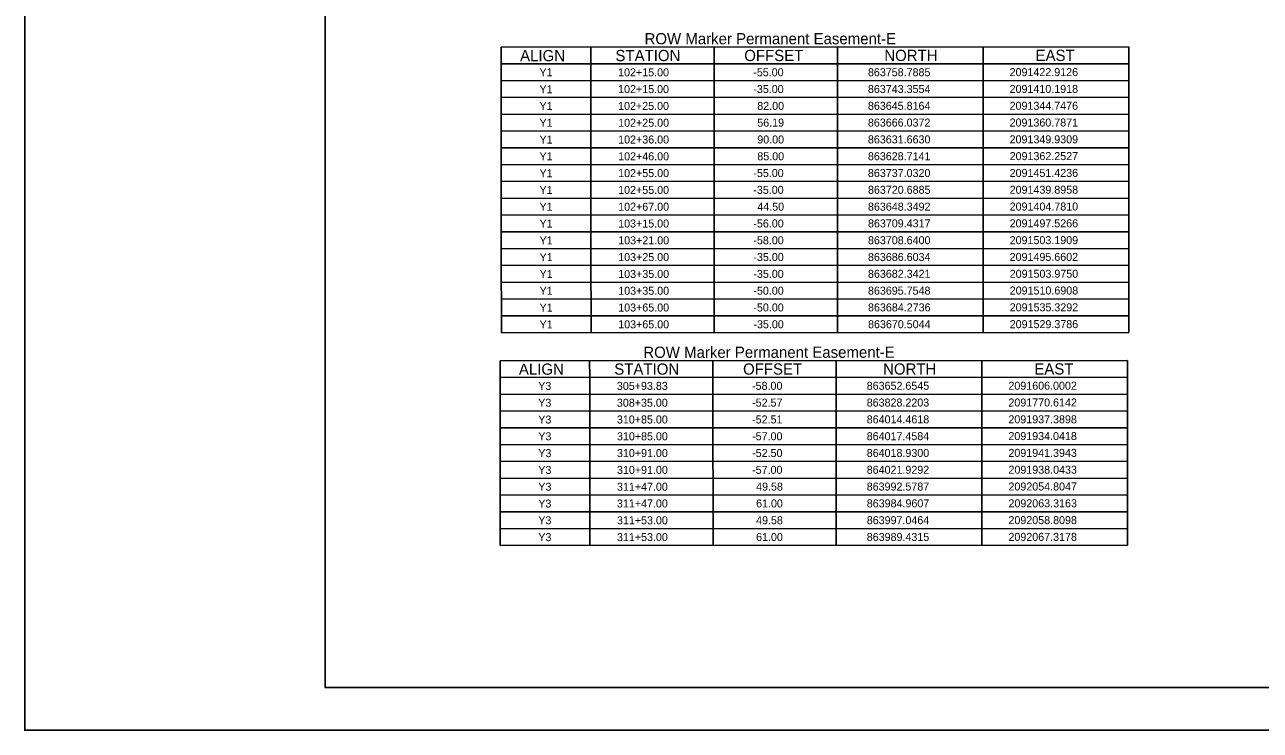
# Model space of a CAD drawing. Extents: x 2093228 to 2098328, y 861854 to 865154.
# Drawn here: x 2093228 to 2095387, y 861854 to 863087 of the extents above; entities that cross this region are included whole.
import ezdxf

# ---------------------------------------------------------------- set-up
doc = ezdxf.new("R2010")
doc.units = 0
for name, color, linetype in [('CTL Sheet Notes CELL', 7, 'Continuous'), ('CTL Sheet Table Cell', 7, 'Continuous'), ('CTL Sheet Text', 7, 'Continuous'), ('Sheet Plan CELL', 7, 'Continuous'), ('Sheet Plot Border Inside CELL', 7, 'Continuous')]:
    doc.layers.add(name, color=color, linetype=linetype)

msp = doc.modelspace()

# ---------------------------------------------------------------- linework, layer by layer
at = {"layer": 'CTL Sheet Table Cell'}
for p, q in [((2094060.9, 863048), (2095157, 863048.5)), ((2094060.9, 863048), (2094060.9, 863018.6)), ((2094217.4, 863048), (2094217.5, 863018.7)), ((2094432.8, 863048.1), (2094432.8, 863018.8)), ((2094648.1, 863048.2), (2094648.1, 863018.9)), ((2094902.5, 863048.4), (2094902.6, 863019)), ((2095157, 863048.5), (2095157, 863019.1)), ((2094060.9, 863018.6), (2095157, 863019.1)), ((2094060.9, 863018.6), (2094060.9, 862989.2)), ((2094217.5, 863018.7), (2094217.5, 862989.3)), ((2094432.8, 863018.8), (2094432.8, 862989.4)), ((2094648.1, 863018.9), (2094648.1, 862989.5)), ((2094902.6, 863019), (2094902.6, 862989.6)), ((2095157, 863019.1), (2095157, 862989.8)), ((2094060.9, 862989.2), (2095157, 862989.8)), ((2094060.9, 862989.2), (2094060.9, 862959.9)), ((2094217.5, 862989.3), (2094217.5, 862960)), ((2094432.8, 862989.4), (2094432.8, 862960.1)), ((2094648.1, 862989.5), (2094648.1, 862960.2)), ((2094902.6, 862989.6), (2094902.6, 862960.3)), ((2095157, 862989.8), (2095157.1, 862960.4)), ((2094060.9, 862959.9), (2095157.1, 862960.4)), ((2094060.9, 862959.9), (2094060.9, 862930.5)), ((2094217.5, 862960), (2094217.5, 862930.6)), ((2094432.8, 862960.1), (2094432.8, 862930.7)), ((2094648.1, 862960.2), (2094648.1, 862930.8)), ((2094902.6, 862960.3), (2094902.6, 862930.9)), ((2095157.1, 862960.4), (2095157.1, 862931)), ((2094060.9, 862930.5), (2095157.1, 862931)), ((2094060.9, 862930.5), (2094060.9, 862901.2)), ((2094217.5, 862930.6), (2094217.5, 862901.2)), ((2094432.8, 862930.7), (2094432.8, 862901.3)), ((2094648.1, 862930.8), (2094648.2, 862901.4)), ((2094902.6, 862930.9), (2094902.6, 862901.6)), ((2095157.1, 862931), (2095157.1, 862901.7)), ((2094060.9, 862901.2), (2095157.1, 862901.7)), ((2094060.9, 862901.2), (2094060.9, 862871.8)), ((2094217.5, 862901.2), (2094217.5, 862871.9)), ((2094432.8, 862901.3), (2094432.8, 862872)), ((2094648.2, 862901.4), (2094648.2, 862872.1)), ((2094902.6, 862901.6), (2094902.6, 862872.2)), ((2095157.1, 862901.7), (2095157.1, 862872.3)), ((2094060.9, 862871.8), (2095157.1, 862872.3)), ((2094060.9, 862871.8), (2094061, 862842.4)), ((2094217.5, 862871.9), (2094217.5, 862842.5)), ((2094432.8, 862872), (2094432.9, 862842.6)), ((2094648.2, 862872.1), (2094648.2, 862842.7)), ((2094902.6, 862872.2), (2094902.6, 862842.8)), ((2095157.1, 862872.3), (2095157.1, 862843)), ((2094061, 862842.4), (2095157.1, 862843)), ((2094061, 862842.4), (2094061, 862813.1)), ((2094217.5, 862842.5), (2094217.6, 862813.1)), ((2094432.9, 862842.6), (2094432.9, 862813.3)), ((2094648.2, 862842.7), (2094648.2, 862813.4)), ((2094902.6, 862842.8), (2094902.7, 862813.5)), ((2095157.1, 862843), (2095157.1, 862813.6)), ((2094061, 862813.1), (2095157.1, 862813.6)), ((2094061, 862813.1), (2094061, 862783.7)), ((2094217.6, 862813.1), (2094217.6, 862783.8)), ((2094432.9, 862813.3), (2094432.9, 862783.9)), ((2094648.2, 862813.4), (2094648.2, 862784)), ((2094902.7, 862813.5), (2094902.7, 862784.1)), ((2095157.1, 862813.6), (2095157.1, 862784.2)), ((2094061, 862783.7), (2095157.1, 862784.2)), ((2094061, 862783.7), (2094061, 862754.3)), ((2094217.6, 862783.8), (2094217.6, 862754.4)), ((2094432.9, 862783.9), (2094432.9, 862754.5)), ((2094648.2, 862784), (2094648.2, 862754.6)), ((2094902.7, 862784.1), (2094902.7, 862754.8)), ((2095157.1, 862784.2), (2095157.2, 862754.9)), ((2094061, 862754.3), (2095157.2, 862754.9)), ((2094061, 862754.3), (2094061, 862725)), ((2094217.6, 862754.4), (2094217.6, 862725.1)), ((2094432.9, 862754.5), (2094432.9, 862725.2)), ((2094648.2, 862754.6), (2094648.2, 862725.3)), ((2094902.7, 862754.8), (2094902.7, 862725.4)), ((2095157.2, 862754.9), (2095157.2, 862725.5)), ((2094061, 862725), (2095157.2, 862725.5)), ((2094061, 862725), (2094061, 862695.6)), ((2094217.6, 862725.1), (2094217.6, 862695.7)), ((2094432.9, 862725.2), (2094432.9, 862695.8)), ((2094648.2, 862725.3), (2094648.3, 862695.9)), ((2094902.7, 862725.4), (2094902.7, 862696)), ((2095157.2, 862725.5), (2095157.2, 862696.2)), ((2094061, 862695.6), (2095157.2, 862696.2)), ((2094061, 862695.6), (2094061, 862666.3)), ((2094217.6, 862695.7), (2094217.6, 862666.3)), ((2094432.9, 862695.8), (2094432.9, 862666.4)), ((2094648.3, 862695.9), (2094648.3, 862666.5)), ((2094902.7, 862696), (2094902.7, 862666.7)), ((2095157.2, 862696.2), (2095157.2, 862666.8)), ((2094061, 862666.3), (2095157.2, 862666.8)), ((2094061, 862666.3), (2094061, 862636.9)), ((2094217.6, 862666.3), (2094217.6, 862637)), ((2094432.9, 862666.4), (2094433, 862637.1)), ((2094648.3, 862666.5), (2094648.3, 862637.2)), ((2094902.7, 862666.7), (2094902.7, 862637.3)), ((2095157.2, 862666.8), (2095157.2, 862637.4)), ((2094061, 862636.9), (2095157.2, 862637.4)), ((2094061, 862636.9), (2094061.1, 862607.5)), ((2094217.6, 862637), (2094217.7, 862607.6)), ((2094433, 862637.1), (2094433, 862607.7)), ((2094648.3, 862637.2), (2094648.3, 862607.8)), ((2094902.7, 862637.3), (2094902.8, 862607.9)), ((2095157.2, 862637.4), (2095157.2, 862608.1)), ((2094061.1, 862607.5), (2095157.2, 862608.1)), ((2094061.1, 862607.5), (2094061.1, 862578.2)), ((2094217.7, 862607.6), (2094217.7, 862578.3)), ((2094433, 862607.7), (2094433, 862578.4)), ((2094648.3, 862607.8), (2094648.3, 862578.5)), ((2094902.8, 862607.9), (2094902.8, 862578.6)), ((2095157.2, 862608.1), (2095157.2, 862578.7)), ((2094061.1, 862578.2), (2095157.2, 862578.7)), ((2094061.1, 862578.2), (2094061.1, 862548.8)), ((2094217.7, 862578.3), (2094217.7, 862548.9)), ((2094433, 862578.4), (2094433, 862549)), ((2094648.3, 862578.5), (2094648.3, 862549.1)), ((2094902.8, 862578.6), (2094902.8, 862549.2)), ((2095157.2, 862578.7), (2095157.3, 862549.3)), ((2094061.1, 862548.8), (2095157.3, 862549.3)), ((2094058.7, 862499.9), (2095154.9, 862500.5)), ((2094058.7, 862499.9), (2094058.8, 862470.6)), ((2094215.3, 862500), (2094215.4, 862470.7)), ((2094430.7, 862500.1), (2094430.7, 862470.8)), ((2094646, 862500.2), (2094646, 862470.9)), ((2094900.4, 862500.4), (2094900.5, 862471)), ((2095154.9, 862500.5), (2095154.9, 862471.1)), ((2094058.8, 862470.6), (2095154.9, 862471.1)), ((2094058.8, 862470.6), (2094058.8, 862441.2)), ((2094215.4, 862470.7), (2094215.4, 862441.3)), ((2094430.7, 862470.8), (2094430.7, 862441.4)), ((2094646, 862470.9), (2094646, 862441.5)), ((2094900.5, 862471), (2094900.5, 862441.6)), ((2095154.9, 862471.1), (2095154.9, 862441.8)), ((2094058.8, 862441.2), (2095154.9, 862441.8)), ((2094058.8, 862441.2), (2094058.8, 862411.9)), ((2094215.4, 862441.3), (2094215.4, 862411.9)), ((2094430.7, 862441.4), (2094430.7, 862412)), ((2094646, 862441.5), (2094646, 862412.1)), ((2094900.5, 862441.6), (2094900.5, 862412.3)), ((2095154.9, 862441.8), (2095155, 862412.4)), ((2094058.8, 862411.9), (2095155, 862412.4)), ((2094058.8, 862411.9), (2094058.8, 862382.5)), ((2094215.4, 862411.9), (2094215.4, 862382.6)), ((2094430.7, 862412), (2094430.7, 862382.7)), ((2094646, 862412.1), (2094646, 862382.8)), ((2094900.5, 862412.3), (2094900.5, 862382.9)), ((2095155, 862412.4), (2095155, 862383)), ((2094058.8, 862382.5), (2095155, 862383)), ((2094058.8, 862382.5), (2094058.8, 862353.1)), ((2094215.4, 862382.6), (2094215.4, 862353.2)), ((2094430.7, 862382.7), (2094430.7, 862353.3)), ((2094646, 862382.8), (2094646, 862353.4)), ((2094900.5, 862382.9), (2094900.5, 862353.5)), ((2095155, 862383), (2095155, 862353.7)), ((2094058.8, 862353.1), (2095155, 862353.7)), ((2094058.8, 862353.1), (2094058.8, 862323.8)), ((2094215.4, 862353.2), (2094215.4, 862323.9)), ((2094430.7, 862353.3), (2094430.7, 862324)), ((2094646, 862353.4), (2094646.1, 862324.1)), ((2094900.5, 862353.5), (2094900.5, 862324.2)), ((2095155, 862353.7), (2095155, 862324.3)), ((2094058.8, 862323.8), (2095155, 862324.3)), ((2094058.8, 862323.8), (2094058.8, 862294.4)), ((2094215.4, 862323.9), (2094215.4, 862294.5)), ((2094430.7, 862324), (2094430.8, 862294.6)), ((2094646.1, 862324.1), (2094646.1, 862294.7)), ((2094900.5, 862324.2), (2094900.5, 862294.8)), ((2095155, 862324.3), (2095155, 862294.9)), ((2094058.8, 862294.4), (2095155, 862294.9)), ((2094058.8, 862294.4), (2094058.9, 862265.1)), ((2094215.4, 862294.5), (2094215.5, 862265.1)), ((2094430.8, 862294.6), (2094430.8, 862265.2)), ((2094646.1, 862294.7), (2094646.1, 862265.3)), ((2094900.5, 862294.8), (2094900.6, 862265.5)), ((2095155, 862294.9), (2095155, 862265.6)), ((2094058.9, 862265.1), (2095155, 862265.6)), ((2094900.6, 862265.5), (2094900.6, 862236.1)), ((2095155, 862265.6), (2095155, 862236.2)), ((2094058.9, 862265.1), (2094058.9, 862235.7)), ((2094215.5, 862265.1), (2094215.5, 862235.8)), ((2094430.8, 862265.2), (2094430.8, 862235.9)), ((2094646.1, 862265.3), (2094646.1, 862236)), ((2094058.9, 862235.7), (2095155, 862236.2)), ((2094058.9, 862235.7), (2094058.9, 862206.3)), ((2094215.5, 862235.8), (2094215.5, 862206.4)), ((2094430.8, 862235.9), (2094430.8, 862206.5)), ((2094646.1, 862236), (2094646.1, 862206.6)), ((2094900.6, 862236.1), (2094900.6, 862206.7)), ((2095155, 862236.2), (2095155.1, 862206.9)), ((2094058.9, 862206.3), (2095155.1, 862206.9)), ((2094058.9, 862206.3), (2094058.9, 862177)), ((2094215.5, 862206.4), (2094215.5, 862177)), ((2094430.8, 862206.5), (2094430.8, 862177.1)), ((2094646.1, 862206.6), (2094646.1, 862177.3)), ((2094900.6, 862206.7), (2094900.6, 862177.4)), ((2095155.1, 862206.9), (2095155.1, 862177.5)), ((2094058.9, 862177), (2095155.1, 862177.5))]:
    msp.add_line(p, q, dxfattribs=at)
at = {"layer": 'Sheet Plan CELL'}
msp.add_lwpolyline([(2093753.4, 865079.1), (2098253.4, 865079.1), (2098253.4, 861929.1), (2093753.4, 861929.1)], close=True, dxfattribs=at)
at = {"layer": 'Sheet Plot Border Inside CELL'}
msp.add_lwpolyline([(2098328.4, 865154.1), (2093228.4, 865154.1), (2093228.4, 861854.1), (2098328.4, 861854.1)], close=True, dxfattribs=at)

# ---------------------------------------------------------------- texts
at = {"layer": 'CTL Sheet Notes CELL'}
for s, height, p in [('ROW Marker Permanent Easement-E', 19.574, (2094311.2, 863053)), ('ALIGN', 19.57, (2094093.8, 863023.5)), ('STATION', 19.57, (2094260.4, 863023.6)), ('OFFSET', 19.57, (2094485.4, 863023.7)), ('NORTH', 19.57, (2094730, 863023.8)), ('EAST', 19.57, (2094994.2, 863023.9)), ('ROW Marker Permanent Easement-E', 19.574, (2094309, 862505)), ('ALIGN', 19.57, (2094091.7, 862475.5)), ('STATION', 19.57, (2094258.3, 862475.6)), ('OFFSET', 19.57, (2094483.3, 862475.7)), ('NORTH', 19.57, (2094727.9, 862475.8)), ('EAST', 19.57, (2094992.1, 862475.9))]:
    msp.add_text(s, height=height, rotation=0.0276, dxfattribs=at).set_placement(p)
at = {"layer": 'CTL Sheet Text'}
for s, height, p in [('Y1', 13.98, (2094127.6, 862997)), ('102+15.00', 13.98, (2094265, 862997)), ('-55.00', 13.98, (2094501.1, 862997.1)), ('863758.7885', 13.982, (2094701.4, 862997.2)), ('2091422.9126', 13.982, (2094948.9, 862997.4)), ('Y1', 13.98, (2094127.6, 862967.6)), ('102+15.00', 13.98, (2094265, 862967.7)), ('-35.00', 13.98, (2094501.2, 862967.8)), ('863743.3554', 13.982, (2094701.4, 862967.9)), ('2091410.1918', 13.982, (2094948.9, 862968)), ('Y1', 13.98, (2094127.6, 862938.2)), ('102+25.00', 13.98, (2094265, 862938.3)), ('82.00', 13.98, (2094508.1, 862938.4)), ('863645.8164', 13.982, (2094701.4, 862938.5)), ('2091344.7476', 13.982, (2094948.9, 862938.6)), ('Y1', 13.98, (2094127.7, 862908.9)), ('102+25.00', 13.98, (2094265.1, 862908.9)), ('56.19', 13.98, (2094508.1, 862909.1)), ('863666.0372', 13.982, (2094701.4, 862909.2)), ('2091360.7871', 13.982, (2094948.9, 862909.3)), ('Y1', 13.98, (2094127.7, 862879.5)), ('102+36.00', 13.98, (2094265.1, 862879.6)), ('90.00', 13.98, (2094508.1, 862879.7)), ('863631.6630', 13.982, (2094701.4, 862879.8)), ('2091349.9309', 13.982, (2094948.9, 862879.9)), ('Y1', 13.98, (2094127.7, 862850.2)), ('102+46.00', 13.98, (2094265.1, 862850.2)), ('85.00', 13.98, (2094508.2, 862850.3)), ('863628.7141', 13.982, (2094701.4, 862850.4)), ('2091362.2527', 13.982, (2094949, 862850.6)), ('Y1', 13.98, (2094127.7, 862820.8)), ('102+55.00', 13.98, (2094265.1, 862820.9)), ('-55.00', 13.98, (2094501.2, 862821)), ('863737.0320', 13.982, (2094701.4, 862821.1)), ('2091451.4236', 13.982, (2094949, 862821.2)), ('Y1', 13.98, (2094127.7, 862791.4)), ('102+55.00', 13.98, (2094265.1, 862791.5)), ('-35.00', 13.98, (2094501.2, 862791.6)), ('863720.6885', 13.982, (2094701.5, 862791.7)), ('2091439.8958', 13.982, (2094949, 862791.8)), ('Y1', 13.98, (2094127.7, 862762.1)), ('102+67.00', 13.98, (2094265.1, 862762.1)), ('44.50', 13.98, (2094508.2, 862762.3)), ('863648.3492', 13.982, (2094701.5, 862762.3)), ('2091404.7810', 13.982, (2094949, 862762.5)), ('Y1', 13.98, (2094127.7, 862732.7)), ('103+15.00', 13.98, (2094265.1, 862732.8)), ('-56.00', 13.98, (2094501.3, 862732.9)), ('863709.4317', 13.982, (2094701.5, 862733)), ('2091497.5266', 13.982, (2094949, 862733.1)), ('Y1', 13.98, (2094127.8, 862703.3)), ('103+21.00', 13.98, (2094265.2, 862703.4)), ('-58.00', 13.98, (2094501.3, 862703.5)), ('863708.6400', 13.982, (2094701.5, 862703.6)), ('2091503.1909', 13.982, (2094949, 862703.7)), ('Y1', 13.98, (2094127.8, 862674)), ('103+25.00', 13.98, (2094265.2, 862674.1)), ('-35.00', 13.98, (2094501.3, 862674.2)), ('863686.6034', 13.982, (2094701.5, 862674.3)), ('2091495.6602', 13.982, (2094949, 862674.4)), ('Y1', 13.98, (2094127.8, 862644.6)), ('103+35.00', 13.98, (2094265.2, 862644.7)), ('-35.00', 13.98, (2094501.3, 862644.8)), ('863682.3421', 13.982, (2094701.5, 862644.9)), ('2091503.9750', 13.982, (2094949.1, 862645)), ('Y1', 13.98, (2094127.8, 862615.3)), ('103+35.00', 13.98, (2094265.2, 862615.3)), ('-50.00', 13.98, (2094501.3, 862615.4)), ('863695.7548', 13.982, (2094701.5, 862615.5)), ('2091510.6908', 13.982, (2094949.1, 862615.7)), ('Y1', 13.98, (2094127.8, 862585.9)), ('103+65.00', 13.98, (2094265.2, 862586)), ('-50.00', 13.98, (2094501.3, 862586.1)), ('863684.2736', 13.982, (2094701.6, 862586.2)), ('2091535.3292', 13.982, (2094949.1, 862586.3)), ('Y1', 13.98, (2094127.8, 862556.5)), ('103+65.00', 13.98, (2094265.2, 862556.6)), ('-35.00', 13.98, (2094501.4, 862556.7)), ('863670.5044', 13.982, (2094701.6, 862556.8)), ('2091529.3786', 13.982, (2094949.1, 862556.9)), ('Y3', 13.98, (2094125.5, 862448.9)), ('305+93.83', 13.98, (2094262.9, 862449)), ('-58.00', 13.98, (2094499, 862449.1)), ('863652.6545', 13.982, (2094699.3, 862449.2)), ('2091606.0002', 13.982, (2094946.8, 862449.3)), ('Y3', 13.98, (2094125.5, 862419.6)), ('308+35.00', 13.98, (2094262.9, 862419.6)), ('-52.57', 13.98, (2094499.1, 862419.8)), ('863828.2203', 13.982, (2094699.3, 862419.9)), ('2091770.6142', 13.982, (2094946.8, 862420)), ('Y3', 13.98, (2094125.5, 862390.2)), ('310+85.00', 13.98, (2094262.9, 862390.3)), ('-52.51', 13.98, (2094499.1, 862390.4)), ('864014.4618', 13.982, (2094699.3, 862390.5)), ('2091937.3898', 13.982, (2094946.8, 862390.6)), ('Y3', 13.98, (2094125.6, 862360.9)), ('310+85.00', 13.98, (2094263, 862360.9)), ('-57.00', 13.98, (2094499.1, 862361)), ('864017.4584', 13.982, (2094699.3, 862361.1)), ('2091934.0418', 13.982, (2094946.8, 862361.3)), ('Y3', 13.98, (2094125.6, 862331.5)), ('310+91.00', 13.98, (2094263, 862331.6)), ('-52.50', 13.98, (2094499.1, 862331.7)), ('864018.9300', 13.982, (2094699.3, 862331.8)), ('2091941.3943', 13.982, (2094946.8, 862331.9)), ('Y3', 13.98, (2094125.6, 862302.1)), ('310+91.00', 13.98, (2094263, 862302.2)), ('-57.00', 13.98, (2094499.1, 862302.3)), ('864021.9292', 13.982, (2094699.3, 862302.4)), ('2091938.0433', 13.982, (2094946.9, 862302.5)), ('311+47.00', 13.98, (2094263, 862272.8)), ('49.58', 13.98, (2094506.1, 862273)), ('863992.5787', 13.982, (2094699.3, 862273.1)), ('2092054.8047', 13.982, (2094946.9, 862273.2)), ('Y3', 13.98, (2094125.6, 862272.8)), ('Y3', 13.98, (2094125.6, 862243.4)), ('311+47.00', 13.98, (2094263, 862243.5)), ('61.00', 13.98, (2094506.1, 862243.6)), ('863984.9607', 13.982, (2094699.4, 862243.7)), ('2092063.3163', 13.982, (2094946.9, 862243.8)), ('Y3', 13.98, (2094125.6, 862214.1)), ('311+53.00', 13.98, (2094263, 862214.1)), ('49.58', 13.98, (2094506.1, 862214.2)), ('863997.0464', 13.982, (2094699.4, 862214.3)), ('2092058.8098', 13.982, (2094946.9, 862214.4)), ('Y3', 13.98, (2094125.6, 862184.7)), ('311+53.00', 13.98, (2094263, 862184.8)), ('61.00', 13.98, (2094506.1, 862184.9)), ('863989.4315', 13.982, (2094699.4, 862185)), ('2092067.3178', 13.982, (2094946.9, 862185.1))]:
    msp.add_text(s, height=height, rotation=0.0276, dxfattribs=at).set_placement(p)

doc.saveas('drawing.dxf')
